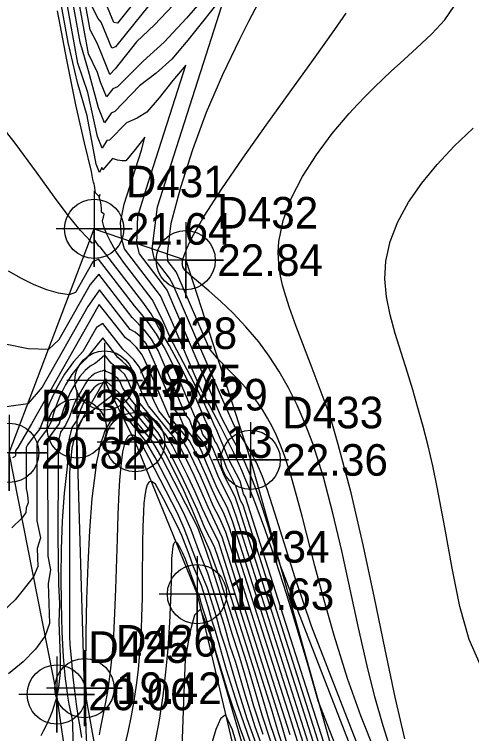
# Model space of a CAD drawing. Extents: x 2356077 to 2359823, y 225951 to 227822.
# Drawn here: x 2356576.9 to 2356613, y 227080.3 to 227137.3 of the extents above; entities that cross this region are included whole.
import ezdxf

# ---------------------------------------------------------------- set-up
doc = ezdxf.new("R2010")
doc.units = 0
for name, color, linetype in [('DTM Contours Major', 7, 'Continuous'), ('DTM Contours Minor', 7, 'Continuous'), ('Exist DTM Breakline', 7, 'Continuous'), ('Exist DTM Breakline Cogo Elevation', 7, 'Continuous'), ('Exist DTM Breakline Cogo Number', 7, 'Continuous'), ('Exist DTM Breakline Cogo Point CELL', 7, 'Continuous'), ('PH Exist DTM Point', 7, 'Continuous')]:
    doc.layers.add(name, color=color, linetype=linetype)

msp = doc.modelspace()

# ---------------------------------------------------------------- linework, layer by layer
at = {"layer": 'DTM Contours Major'}
for points in [[(2356604.65, 227073.288), (2356600.899, 227082.925), (2356600.105, 227085.727), (2356599.275, 227088.544), (2356598.419, 227091.323), (2356597.548, 227094.008), (2356596.67, 227096.546), (2356595.796, 227098.881), (2356595.567, 227099.457), (2356595.338, 227100.018), (2356595.108, 227100.564), (2356594.877, 227101.099), (2356594.645, 227101.623), (2356594.211, 227102.561), (2356593.807, 227103.399), (2356593.389, 227104.232), (2356593.175, 227104.65), (2356592.313, 227106.275), (2356591.542, 227107.757), (2356589.281, 227113.034), (2356588.432, 227114.972), (2356585.565, 227118.688), (2356585.338, 227119.537), (2356585.241, 227120.781), (2356585.552, 227122.22), (2356586.925, 227126.502), (2356587.175, 227127.521), (2356586.401, 227126.547), (2356585.667, 227125.658), (2356585.38, 227125.673), (2356585.02, 227125.707), (2356584.607, 227125.841), (2356583.848, 227124.955), (2356583.777, 227125.124), (2356583.599, 227124.745), (2356583.331, 227125.41), (2356582.62, 227129.212), (2356581.85, 227131.856), (2356581.11, 227135.035), (2356579.76, 227142.44)], [(2356587.502, 227137.943), (2356586.273, 227136.462), (2356584.869, 227134.693), (2356584.554, 227134.571), (2356583.719, 227136.647), (2356583.46, 227136.962), (2356582.986, 227137.919)], [(2356607.769, 227079.922), (2356607.001, 227083.209), (2356606.203, 227086.994), (2356605.365, 227091.082), (2356604.475, 227095.279), (2356603.522, 227099.387), (2356602.494, 227103.214), (2356601.84, 227105.454), (2356600.426, 227109.259), (2356599.162, 227112.559), (2356598.628, 227114.038), (2356598.331, 227114.948), (2356598.083, 227115.83), (2356597.895, 227116.693), (2356597.776, 227117.547), (2356597.735, 227118.404), (2356597.784, 227119.272), (2356598.13, 227120.949), (2356598.773, 227122.672), (2356599.666, 227124.412), (2356600.76, 227126.136), (2356602.007, 227127.813), (2356603.36, 227129.413), (2356604.013, 227130.125), (2356604.677, 227130.814), (2356605.349, 227131.484), (2356606.026, 227132.137), (2356606.706, 227132.774), (2356607.387, 227133.398), (2356608.688, 227134.575), (2356609.895, 227135.714), (2356610.921, 227136.82), (2356611.676, 227137.899)], [(2356600.149, 227078.23), (2356594.122, 227097.153), (2356593.698, 227098.243), (2356592.914, 227099.766), (2356592.071, 227101.747), (2356591.653, 227102.698), (2356591.319, 227103.361), (2356590.269, 227104.65), (2356589.929, 227105.52), (2356589.574, 227105.93), (2356587.692, 227110.321), (2356587.277, 227111.208), (2356586.807, 227111.754), (2356586.416, 227112.092), (2356586.019, 227112.316), (2356583.602, 227115.445), (2356582.669, 227114.127), (2356579.053, 227107.744), (2356577.924, 227106.433), (2356575.427, 227106.093)], [(2356597.757, 227079.173), (2356597.104, 227081.102), (2356596.499, 227083.19), (2356595.883, 227085.204), (2356593.342, 227093.176), (2356592.698, 227095.122), (2356591.966, 227096.546), (2356591.335, 227098.028), (2356590.7, 227099.447), (2356590.055, 227100.798), (2356589.405, 227102.076), (2356588.754, 227103.275), (2356588.224, 227104.123), (2356585.874, 227107.008), (2356585.399, 227107.729), (2356585.188, 227108.221), (2356585.049, 227108.437), (2356584.842, 227108.602), (2356584.64, 227108.739), (2356584.442, 227108.849), (2356584.128, 227108.978), (2356584.025, 227109.111), (2356583.812, 227109.008), (2356583.654, 227108.984), (2356583.501, 227108.947), (2356583.227, 227108.824), (2356582.958, 227108.632), (2356582.694, 227108.372), (2356582.473, 227108.033), (2356581.987, 227107.176), (2356581.691, 227106.674), (2356581.449, 227106.075), (2356581.226, 227105.41), (2356580.91, 227104.74), (2356580.493, 227104.177), (2356580.326, 227103.411), (2356580.33, 227099.712), (2356580.294, 227097.873), (2356580.288, 227095.979), (2356580.322, 227094.067), (2356580.338, 227092.12), (2356580.414, 227090.631), (2356580.381, 227089.118), (2356580.472, 227086.402), (2356580.47, 227085.178), (2356580.335, 227084.002), (2356580.257, 227083.562), (2356580.213, 227083.348), (2356580.108, 227082.915), (2356579.985, 227082.495), (2356579.845, 227082.082), (2356579.686, 227081.675), (2356579.508, 227081.268), (2356579.311, 227080.859), (2356579.133, 227080.513), (2356578.94, 227080.162)], [(2356595.552, 227079.654), (2356594.569, 227082.469), (2356593.65, 227085.386), (2356592.768, 227088.431), (2356592.452, 227089.383), (2356592.192, 227090.362), (2356591.653, 227092.055), (2356591.03, 227093.52), (2356590.677, 227094.5), (2356590.097, 227096.014), (2356589.756, 227096.749), (2356588.646, 227098.906), (2356588.032, 227100.071), (2356587.677, 227100.304), (2356587.499, 227100.237), (2356587.359, 227100.011), (2356587.252, 227099.643), (2356587.171, 227099.153), (2356587.113, 227098.557), (2356587.071, 227097.875), (2356587.029, 227096.694), (2356587.005, 227095.387), (2356586.978, 227092.533), (2356586.958, 227091.058), (2356586.921, 227089.597), (2356586.882, 227088.606), (2356586.829, 227087.636), (2356586.762, 227086.687), (2356586.643, 227085.404), (2356586.493, 227084.154), (2356586.313, 227082.934), (2356586.102, 227081.744), (2356585.86, 227080.58), (2356585.587, 227079.442)]]:
    msp.add_lwpolyline(points, dxfattribs=at)
at = {"layer": 'DTM Contours Minor'}
for points in [[(2356592.258, 227138.996), (2356590.486, 227136.943), (2356588.722, 227135.051), (2356587.047, 227133.542), (2356585.022, 227131.505), (2356584.658, 227131.36), (2356584.137, 227130.727), (2356583.67, 227131.888), (2356583.445, 227132.659), (2356582.716, 227134.133), (2356580.294, 227147.421)], [(2356589.434, 227137.968), (2356587.932, 227136.411), (2356586.526, 227135.089), (2356584.82, 227132.941), (2356584.403, 227132.506), (2356583.671, 227134.328), (2356583.393, 227134.964), (2356582.851, 227136.026), (2356580.774, 227147.422)], [(2356605.154, 227076.532), (2356600.369, 227088.827), (2356599.077, 227092.666), (2356597.48, 227097.77), (2356597.073, 227099.031), (2356596.885, 227099.589), (2356596.704, 227100.102), (2356596.482, 227100.69), (2356596.261, 227101.227), (2356596.148, 227101.481), (2356596.033, 227101.728), (2356595.897, 227102.003), (2356595.755, 227102.275), (2356595.606, 227102.547), (2356595.448, 227102.822), (2356595.098, 227103.399), (2356594.254, 227104.704), (2356593.248, 227106.954), (2356589.432, 227115.86), (2356589.137, 227116.373), (2356587.917, 227117.954), (2356587.765, 227118.707), (2356588.18, 227122.018), (2356592.67, 227136.028), (2356593.627, 227139.026), (2356590.594, 227135.208), (2356589.319, 227133.718), (2356588.08, 227132.594), (2356586.765, 227131.6), (2356584.815, 227129.553), (2356584.516, 227129.439), (2356583.986, 227128.663), (2356583.509, 227129.848), (2356582.719, 227132.786), (2356582.068, 227135.052), (2356579.866, 227147.13)], [(2356605.68, 227073.627), (2356597.909, 227093.597), (2356597.376, 227095.352), (2356596.909, 227096.868), (2356596.487, 227098.187), (2356596.09, 227099.349), (2356595.698, 227100.397), (2356595.29, 227101.372), (2356595.062, 227101.872), (2356594.822, 227102.37), (2356594.456, 227103.083), (2356594.104, 227103.731), (2356593.853, 227104.179), (2356593.259, 227105.338), (2356588.934, 227115.432), (2356588.506, 227116.034), (2356586.763, 227118.293), (2356586.552, 227119.122), (2356586.631, 227121.281), (2356587.445, 227123.925), (2356590.43, 227133.239), (2356589.399, 227132.012), (2356588.305, 227130.634), (2356587.334, 227129.502), (2356586.569, 227129.031), (2356585.733, 227128.674), (2356584.372, 227127.306), (2356584.176, 227127.283), (2356583.807, 227126.667), (2356583.433, 227127.598), (2356582.676, 227131.059), (2356581.888, 227133.402), (2356579.49, 227146.562)], [(2356587.325, 227139.477), (2356585.014, 227136.567), (2356584.721, 227136.597), (2356584.098, 227138.147)], [(2356605.453, 227078.751), (2356604.29, 227081.74), (2356603.214, 227084.7), (2356602.166, 227088.108), (2356601.222, 227091.443), (2356600.646, 227093.613), (2356599.633, 227097.543), (2356599.164, 227099.293), (2356598.701, 227100.892), (2356598.226, 227102.335), (2356597.915, 227103.159), (2356597.591, 227103.926), (2356597.252, 227104.638), (2356596.896, 227105.303), (2356596.521, 227105.924), (2356596.124, 227106.507), (2356595.643, 227107.133), (2356595.137, 227107.727), (2356594.609, 227108.3), (2356594.066, 227108.862), (2356592.951, 227109.998), (2356592.286, 227110.789), (2356589.804, 227116.581), (2356589.652, 227116.864), (2356588.99, 227117.721), (2356588.978, 227118.292), (2356589.263, 227120.715), (2356590.026, 227123.577), (2356590.98, 227126.553), (2356592.072, 227129.518), (2356593.365, 227132.503), (2356594.688, 227135.283), (2356595.436, 227136.754), (2356596.151, 227138.106)], [(2356601.924, 227077.81), (2356595.155, 227099.052), (2356594.998, 227099.296), (2356594.713, 227100.321), (2356593.856, 227101.985), (2356593.611, 227102.546), (2356593.377, 227103.125), (2356593.139, 227103.694), (2356592.897, 227104.256), (2356592.65, 227104.814), (2356592.397, 227105.369), (2356591.618, 227107.005), (2356590.795, 227108.632), (2356589.938, 227110.238), (2356589.198, 227111.639), (2356588.602, 227113.029), (2356587.76, 227114.687), (2356585.48, 227117.641), (2356584.881, 227118.521), (2356584.449, 227119.281), (2356584.125, 227119.951), (2356583.942, 227120.454), (2356583.833, 227120.891), (2356583.957, 227121.444), (2356583.757, 227121.603), (2356583.749, 227121.892), (2356583.734, 227122.147), (2356583.702, 227122.349), (2356583.649, 227122.554), (2356583.576, 227122.783), (2356583.631, 227122.991), (2356583.535, 227122.87), (2356583.263, 227123.139), (2356583.203, 227123.707), (2356583.165, 227123.811), (2356583.122, 227123.972), (2356583.074, 227124.19), (2356582.954, 227124.811), (2356582.395, 227127.091), (2356581.729, 227130.098), (2356581, 227133.643), (2356580.253, 227137.538)], [(2356606.714, 227078.859), (2356606.042, 227080.942), (2356605.392, 227083.243), (2356604.774, 227085.692), (2356604.087, 227088.698), (2356602.766, 227094.797), (2356602.073, 227097.775), (2356601.318, 227100.627), (2356600.471, 227103.296), (2356599.88, 227104.856), (2356599.241, 227106.324), (2356598.553, 227107.703), (2356597.817, 227108.996), (2356597.03, 227110.205), (2356596.194, 227111.333), (2356595.187, 227112.524), (2356594.16, 227113.603), (2356593.162, 227114.561), (2356592.239, 227115.386), (2356591.437, 227116.068), (2356590.805, 227116.597), (2356590.627, 227116.749), (2356590.478, 227116.886), (2356590.356, 227117.014), (2356590.262, 227117.139), (2356590.196, 227117.269), (2356590.157, 227117.407), (2356590.149, 227117.474), (2356590.146, 227117.545), (2356590.149, 227117.62), (2356590.172, 227117.786), (2356590.191, 227117.877), (2356590.308, 227118.257), (2356590.494, 227118.716), (2356590.747, 227119.251), (2356591.065, 227119.858), (2356591.445, 227120.532), (2356591.886, 227121.27), (2356593.276, 227123.436), (2356594.942, 227125.879), (2356596.777, 227128.48), (2356598.672, 227131.12), (2356600.518, 227133.682), (2356602.207, 227136.046), (2356603.106, 227137.334)], [(2356602.307, 227075.32), (2356594.951, 227098.406), (2356594.742, 227098.783), (2356594.394, 227099.927), (2356593.934, 227100.822), (2356593.67, 227101.35), (2356593.37, 227102.115), (2356593.12, 227102.728), (2356592.889, 227103.255), (2356592.716, 227103.467), (2356592.413, 227104.245), (2356592.175, 227104.708), (2356591.927, 227105.206), (2356591.23, 227106.833), (2356590.529, 227108.367), (2356589.838, 227109.71), (2356589.126, 227111.015), (2356588.396, 227112.269), (2356587.691, 227113.566), (2356587.03, 227114.475), (2356583.65, 227118.855), (2356583.525, 227118.901), (2356583.228, 227119.383), (2356583.104, 227119.164), (2356583.001, 227119.158), (2356582.821, 227119.349), (2356582.581, 227119.609), (2356582.095, 227120.151), (2356581.846, 227120.44), (2356581.59, 227120.745), (2356581.127, 227121.321), (2356580.708, 227121.863), (2356580.028, 227122.777), (2356578.594, 227124.762), (2356576.913, 227127.046), (2356574.989, 227129.481)], [(2356613.723, 227085.802), (2356612.842, 227087.785), (2356612.121, 227090.401), (2356611.501, 227093.43), (2356610.922, 227096.651), (2356610.326, 227099.846), (2356609.972, 227101.514), (2356609.597, 227103.113), (2356609.206, 227104.647), (2356608.801, 227106.122), (2356608.385, 227107.542), (2356607.962, 227108.912), (2356607.46, 227110.482), (2356606.991, 227111.999), (2356606.597, 227113.471), (2356606.316, 227114.909), (2356606.189, 227116.321), (2356606.256, 227117.716), (2356606.6, 227119.287), (2356607.212, 227120.843), (2356608.057, 227122.378), (2356609.103, 227123.888), (2356610.317, 227125.367), (2356611.666, 227126.809), (2356613.168, 227128.257)], [(2356601.609, 227076.225), (2356594.687, 227097.95), (2356594.317, 227099.065), (2356593.476, 227100.7), (2356592.803, 227102.344), (2356592.523, 227103.01), (2356592.282, 227103.394), (2356591.783, 227104.005), (2356591.467, 227104.889), (2356591.202, 227105.309), (2356589.336, 227109.663), (2356588.717, 227110.91), (2356588.095, 227111.934), (2356587.464, 227112.847), (2356586.935, 227113.504), (2356586.36, 227114.186), (2356583.501, 227117.891), (2356583.06, 227117.665), (2356581.69, 227115.246), (2356581.189, 227115.044), (2356580.335, 227115.185), (2356579.41, 227115.455), (2356578.432, 227115.844), (2356577.42, 227116.336), (2356576.39, 227116.921)], [(2356600.882, 227077.222), (2356594.407, 227097.543), (2356594.011, 227098.647), (2356593.347, 227099.938), (2356592.989, 227100.706), (2356592.607, 227101.638), (2356592.229, 227102.529), (2356591.92, 227103.231), (2356591.029, 227104.324), (2356590.706, 227105.184), (2356590.4, 227105.59), (2356588.232, 227110.651), (2356587.701, 227111.552), (2356587.156, 227112.259), (2356586.172, 227113.273), (2356583.534, 227116.69), (2356582.857, 227115.883), (2356580.365, 227111.484), (2356579.557, 227110.738), (2356577.935, 227110.771), (2356576.111, 227111.164)], [(2356599.413, 227079.242), (2356598.512, 227082.09), (2356593.858, 227096.699), (2356593.395, 227097.819), (2356592.953, 227098.678), (2356592.497, 227099.642), (2356592.026, 227100.749), (2356591.558, 227101.802), (2356591.092, 227102.806), (2356590.713, 227103.497), (2356589.088, 227105.491), (2356588.715, 227106.345), (2356587.428, 227109.349), (2356586.975, 227110.308), (2356586.515, 227110.885), (2356586.05, 227111.353), (2356585.661, 227111.646), (2356585.278, 227112.117), (2356583.998, 227113.775), (2356583.561, 227114.28), (2356578.215, 227104.841), (2356577.13, 227102.982), (2356576.993, 227102.797), (2356576.941, 227102.715), (2356576.941, 227102.433), (2356576.947, 227102.354), (2356576.945, 227102.312), (2356576.855, 227102.246), (2356576.701, 227102.167)], [(2356598.68, 227080.247), (2356597.85, 227082.885), (2356593.586, 227096.267), (2356593.085, 227097.408), (2356592.592, 227098.366), (2356592.083, 227099.577), (2356591.573, 227100.74), (2356591.063, 227101.843), (2356590.554, 227102.892), (2356590.127, 227103.61), (2356588.279, 227105.877), (2356587.879, 227106.707), (2356586.751, 227109.34), (2356586.312, 227109.903), (2356585.868, 227110.371), (2356585.431, 227110.761), (2356583.867, 227112.787), (2356583.35, 227112.484), (2356582.273, 227110.582), (2356581.521, 227109.767), (2356580.818, 227108.788), (2356580.177, 227107.672), (2356579.626, 227106.48), (2356579.189, 227105.271), (2356578.869, 227104.443), (2356578.348, 227103.791), (2356577.897, 227103.182), (2356577.787, 227102.973), (2356577.79, 227099.72), (2356577.857, 227099.349), (2356577.915, 227098.975), (2356577.953, 227098.599), (2356577.797, 227098.2), (2356577.754, 227097.821), (2356577.458, 227097.419), (2356576.663, 227096.624)], [(2356599.349, 227076.41), (2356597.948, 227081.243), (2356597.191, 227083.669), (2356593.297, 227095.889), (2356592.185, 227098.24), (2356591.634, 227099.529), (2356591.079, 227100.751), (2356590.523, 227101.909), (2356589.967, 227103.005), (2356589.502, 227103.769), (2356587.468, 227106.265), (2356587.04, 227107.077), (2356586.467, 227108.414), (2356586.134, 227109.065), (2356585.764, 227109.469), (2356585.393, 227109.814), (2356585.042, 227110.108), (2356583.851, 227111.651), (2356583.29, 227110.956), (2356582.521, 227109.98), (2356581.946, 227109.438), (2356581.398, 227108.744), (2356580.894, 227107.93), (2356580.449, 227107.027), (2356580.08, 227106.067), (2356579.934, 227105.597), (2356579.809, 227105.121), (2356579.468, 227104.466), (2356578.767, 227103.52), (2356578.633, 227103.183), (2356578.639, 227097.16), (2356578.925, 227095.819), (2356578.664, 227094.991), (2356578.712, 227093.569), (2356578.374, 227092.747), (2356576.919, 227090.926), (2356574.97, 227089.111)], [(2356598.353, 227078.633), (2356597.749, 227080.403), (2356597.205, 227082.282), (2356596.528, 227084.465), (2356593.003, 227095.527), (2356592.37, 227096.773), (2356591.753, 227098.122), (2356591.161, 227099.473), (2356590.563, 227100.758), (2356589.961, 227101.974), (2356589.359, 227103.122), (2356588.863, 227103.947), (2356586.664, 227106.645), (2356586.21, 227107.423), (2356585.811, 227108.355), (2356585.565, 227108.773), (2356585.272, 227109.054), (2356584.984, 227109.291), (2356584.697, 227109.482), (2356584.503, 227109.649), (2356584.011, 227110.286), (2356583.597, 227109.911), (2356583.285, 227109.649), (2356582.862, 227109.419), (2356582.447, 227109.064), (2356582.045, 227108.596), (2356581.663, 227108.025), (2356581.306, 227107.369), (2356580.982, 227106.636), (2356580.778, 227106.085), (2356580.595, 227105.502), (2356580.386, 227104.87), (2356579.597, 227103.803), (2356579.479, 227103.252), (2356579.489, 227094.366), (2356579.704, 227093.29), (2356579.518, 227092.211), (2356579.623, 227089.038), (2356579.29, 227088.075), (2356578.522, 227087.005), (2356577.537, 227086.009), (2356576.386, 227085.056)], [(2356597.16, 227079.713), (2356596.464, 227081.794), (2356595.801, 227084.071), (2356595.243, 227085.926), (2356592.964, 227093.079), (2356592.331, 227094.824), (2356591.598, 227096.488), (2356590.939, 227098.064), (2356590.26, 227099.578), (2356589.566, 227101.02), (2356588.863, 227102.377), (2356588.174, 227103.577), (2356585.087, 227107.366), (2356584.21, 227108.151), (2356584.095, 227108.418), (2356584.173, 227108.083), (2356584.096, 227108.091), (2356584.02, 227108.094), (2356583.944, 227108.091), (2356583.87, 227108.083), (2356583.796, 227108.069), (2356583.663, 227108.031), (2356583.533, 227107.975), (2356583.405, 227107.902), (2356583.279, 227107.811), (2356583.154, 227107.703), (2356583.03, 227107.577), (2356582.727, 227107.162), (2356582.388, 227106.604), (2356582.091, 227105.943), (2356581.815, 227105.177), (2356581.391, 227104.554), (2356581.172, 227103.574), (2356581.025, 227101.453), (2356580.798, 227099.363), (2356580.647, 227097.16), (2356580.563, 227094.919), (2356580.534, 227092.72), (2356580.549, 227090.64), (2356580.574, 227089.485), (2356580.611, 227088.398), (2356580.66, 227087.375), (2356580.721, 227086.415), (2356580.795, 227085.515), (2356580.882, 227084.672), (2356580.97, 227083.966), (2356581.07, 227083.292), (2356581.176, 227082.669), (2356581.294, 227082.056), (2356581.422, 227081.443), (2356581.441, 227081.064), (2356581.509, 227078.763)], [(2356596.546, 227080.256), (2356595.815, 227082.513), (2356595.112, 227084.924), (2356594.611, 227086.624), (2356594.105, 227088.23), (2356593.599, 227089.921), (2356593.084, 227091.597), (2356592.554, 227093.258), (2356592, 227094.902), (2356591.374, 227096.643), (2356588.548, 227102.135), (2356587.773, 227103.462), (2356585.124, 227106.713), (2356584.584, 227107.085), (2356582.264, 227105.297), (2356582.085, 227104.957), (2356581.921, 227104.593), (2356581.771, 227104.207), (2356581.634, 227103.798), (2356581.511, 227103.366), (2356581.399, 227102.911), (2356581.208, 227100.997), (2356581.222, 227088.413), (2356581.205, 227088.03), (2356581.244, 227087.395), (2356581.365, 227086.037), (2356581.492, 227084.788), (2356581.617, 227083.715), (2356581.756, 227082.662), (2356581.915, 227081.586), (2356582.005, 227081.025), (2356582.175, 227080.012)], [(2356596.765, 227078.525), (2356595.924, 227080.871), (2356595.136, 227083.312), (2356594.371, 227085.953), (2356593.92, 227087.337), (2356593.483, 227088.88), (2356592.16, 227093.033), (2356591.516, 227094.678), (2356590.846, 227096.456), (2356590.24, 227097.833), (2356588.008, 227102.172), (2356587.242, 227103.507), (2356585.967, 227105.072), (2356585.657, 227105.443), (2356585.362, 227105.523), (2356585.107, 227105.508), (2356584.863, 227105.413), (2356584.632, 227105.24), (2356584.414, 227104.992), (2356584.211, 227104.672), (2356584.023, 227104.283), (2356583.869, 227103.884), (2356583.727, 227103.436), (2356583.596, 227102.939), (2356583.476, 227102.395), (2356583.365, 227101.806), (2356583.262, 227101.174), (2356582.993, 227098.932), (2356582.794, 227096.4), (2356582.654, 227093.704), (2356582.564, 227090.968), (2356582.512, 227088.319), (2356582.485, 227085.443), (2356582.482, 227083.447), (2356582.495, 227081.834), (2356582.521, 227080.582), (2356582.577, 227079.045)], [(2356596.197, 227078.952), (2356595.289, 227081.51), (2356594.432, 227084.216), (2356593.596, 227087.101), (2356593.206, 227088.27), (2356592.851, 227089.579), (2356592.132, 227091.836), (2356591.499, 227093.375), (2356591.018, 227094.688), (2356590.301, 227096.563), (2356589.755, 227097.765), (2356587.484, 227102.178), (2356586.825, 227103.411), (2356586.592, 227103.698), (2356586.477, 227103.813), (2356586.358, 227103.891), (2356586.246, 227103.94), (2356586.14, 227103.96), (2356586.051, 227103.952), (2356585.967, 227103.92), (2356585.889, 227103.865), (2356585.815, 227103.787), (2356585.747, 227103.687), (2356585.683, 227103.565), (2356585.538, 227103.157), (2356585.42, 227102.622), (2356585.324, 227101.974), (2356585.246, 227101.226), (2356585.182, 227100.389), (2356585.129, 227099.476), (2356585.05, 227097.684), (2356584.984, 227095.758), (2356584.86, 227091.782), (2356584.786, 227089.872), (2356584.693, 227088.109), (2356584.614, 227087), (2356584.569, 227086.482), (2356584.521, 227085.987), (2356584.471, 227085.513), (2356584.416, 227085.06), (2356584.331, 227084.422), (2356584.238, 227083.819), (2356584.141, 227083.244), (2356584.039, 227082.688), (2356583.647, 227080.702), (2356583.562, 227080.229)], [(2356595.906, 227077.539), (2356594.762, 227080.694), (2356593.737, 227083.668), (2356592.846, 227086.634), (2356592.007, 227089.53), (2356591.836, 227090.069), (2356591.659, 227090.588), (2356591.54, 227091.123), (2356591.288, 227091.668), (2356591.076, 227092.235), (2356590.905, 227092.741), (2356590.639, 227093.49), (2356590.39, 227094.137), (2356590.161, 227094.671), (2356589.957, 227095.082), (2356589.78, 227095.359), (2356589.633, 227095.489), (2356589.556, 227095.492), (2356589.492, 227095.433), (2356589.439, 227095.317), (2356589.396, 227095.148), (2356589.361, 227094.93), (2356589.334, 227094.668), (2356589.301, 227094.186), (2356589.278, 227093.617), (2356589.224, 227091.473), (2356589.189, 227090.341), (2356589.133, 227089.086), (2356589.115, 227088.76), (2356588.996, 227087.029), (2356588.825, 227085.203), (2356588.596, 227083.313), (2356588.303, 227081.39), (2356587.939, 227079.466)], [(2356596.511, 227073.924), (2356592.437, 227087.983), (2356591.592, 227090.168), (2356591.122, 227089.716), (2356590.73, 227088.333), (2356590.375, 227086.225), (2356590.234, 227082.903), (2356589.99, 227076.226)], [(2356596.569, 227072.194), (2356594.128, 227080.619), (2356593.568, 227081.82), (2356593.164, 227081.492), (2356592.791, 227080.666), (2356592.424, 227079.426)]]:
    msp.add_lwpolyline(points, dxfattribs=at)
at = {"layer": 'Exist DTM Breakline'}
for points in [[(2356592.929, 227013.119), (2356584.678, 227052.34), (2356580.201, 227083.43), (2356576.451, 227102.549), (2356583.173, 227120.277), (2356590.413, 227117.802), (2356595.556, 227101.99), (2356603.689, 227072.972), (2356610.454, 227075.196)], [(2356596.018, 227014.113), (2356588.008, 227052.967), (2356582.396, 227083.926), (2356581.788, 227104.479), (2356583.994, 227108.268), (2356586.417, 227103.404), (2356591.309, 227091.365), (2356596.499, 227069.437), (2356605.464, 227067.142)]]:
    msp.add_lwpolyline(points, dxfattribs=at)
at = {"layer": 'Exist DTM Breakline Cogo Point CELL'}
for points in [[(2356583.173, 227123.277), (2356583.173, 227117.277), (2356583.173, 227120.277), (2356586.173, 227120.277), (2356580.173, 227120.277)], [(2356590.413, 227120.802), (2356590.413, 227114.802), (2356590.413, 227117.802), (2356593.413, 227117.802), (2356587.413, 227117.802)], [(2356583.994, 227111.268), (2356583.994, 227105.268), (2356583.994, 227108.268), (2356586.994, 227108.268), (2356580.994, 227108.268)], [(2356581.788, 227107.479), (2356581.788, 227101.479), (2356581.788, 227104.479), (2356584.788, 227104.479), (2356578.788, 227104.479)], [(2356586.417, 227106.404), (2356586.417, 227100.404), (2356586.417, 227103.404), (2356589.417, 227103.404), (2356583.417, 227103.404)], [(2356576.451, 227105.549), (2356576.451, 227099.549), (2356576.451, 227102.549), (2356579.451, 227102.549), (2356573.451, 227102.549)], [(2356595.556, 227104.99), (2356595.556, 227098.99), (2356595.556, 227101.99), (2356598.556, 227101.99), (2356592.556, 227101.99)], [(2356591.309, 227094.365), (2356591.309, 227088.365), (2356591.309, 227091.365), (2356594.309, 227091.365), (2356588.309, 227091.365)], [(2356582.396, 227086.926), (2356582.396, 227080.926), (2356582.396, 227083.926), (2356585.396, 227083.926), (2356579.396, 227083.926)], [(2356580.201, 227086.43), (2356580.201, 227080.43), (2356580.201, 227083.43), (2356583.201, 227083.43), (2356577.201, 227083.43)]]:
    msp.add_lwpolyline(points, dxfattribs=at)
for centre in [(2356583.173, 227120.277), (2356590.413, 227117.802), (2356583.994, 227108.268), (2356581.788, 227104.479), (2356586.417, 227103.404), (2356576.451, 227102.549), (2356595.556, 227101.99), (2356591.309, 227091.365), (2356582.396, 227083.926), (2356580.201, 227083.43)]:
    msp.add_circle(centre, 2.344, dxfattribs=at)
at = {"layer": 'PH Exist DTM Point'}
for p, q in [((2356606.104, 227132.492), (2356606.104, 227132.492)), ((2356599.807, 227117.231), (2356599.807, 227117.231)), ((2356604.198, 227105.706), (2356604.198, 227105.706))]:
    msp.add_line(p, q, dxfattribs=at)

# ---------------------------------------------------------------- texts
at = {"layer": 'Exist DTM Breakline Cogo Elevation'}
for s, p in [('21.64', (2356585.673, 227119.027)), ('22.84', (2356592.913, 227116.552)), ('19.75', (2356586.494, 227107.018)), ('19.56', (2356584.288, 227103.229)), ('19.13', (2356588.917, 227102.154)), ('20.82', (2356578.951, 227101.299)), ('22.36', (2356598.056, 227100.74)), ('18.63', (2356593.809, 227090.116)), ('19.42', (2356584.896, 227082.676)), ('20.00', (2356582.701, 227082.18))]:
    msp.add_text(s, height=2.5, dxfattribs=at).set_placement(p)
at = {"layer": 'Exist DTM Breakline Cogo Number'}
for s, p in [('D431', (2356585.673, 227122.777)), ('D432', (2356592.913, 227120.302)), ('D428', (2356586.494, 227110.768)), ('D427', (2356584.288, 227106.979)), ('D429', (2356588.917, 227105.904)), ('D430', (2356578.951, 227105.049)), ('D433', (2356598.056, 227104.49)), ('D434', (2356593.809, 227093.866)), ('D426', (2356584.896, 227086.426)), ('D425', (2356582.701, 227085.93))]:
    msp.add_text(s, height=2.5, dxfattribs=at).set_placement(p)

doc.saveas('drawing.dxf')
